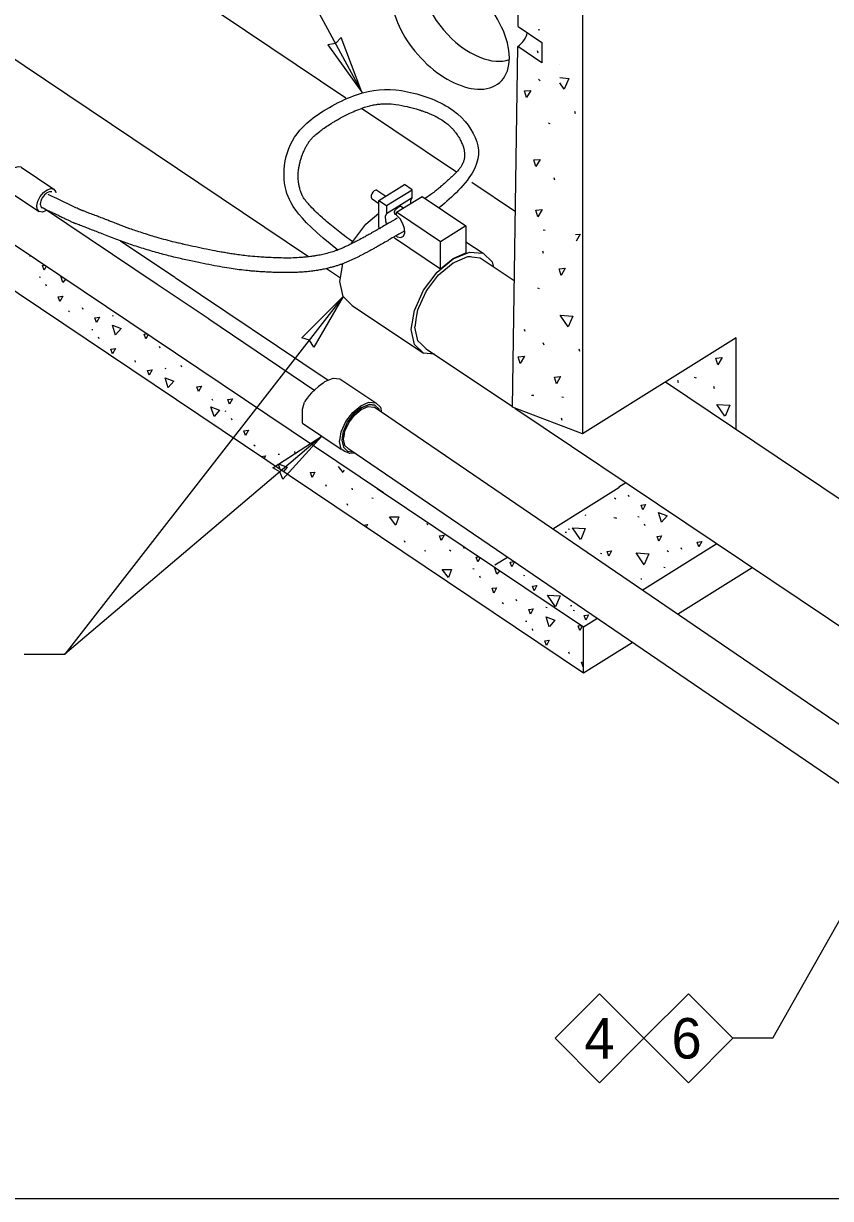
# Model space of a CAD drawing. Extents: x 99862 to 103151, y 100000 to 105076.
# Drawn here: x 100809.4 to 101128.2, y 99999.5 to 100464 of the extents above; entities that cross this region are included whole.
import ezdxf

# ---------------------------------------------------------------- set-up
doc = ezdxf.new("R2010")
doc.units = 0
for name, color, linetype in [('Level 1', 7, 'Continuous'), ('Level 15', 7, 'Continuous'), ('Level 2', 7, 'Continuous'), ('Level 20', 7, 'Continuous'), ('Level 8', 7, 'Continuous')]:
    doc.layers.add(name, color=color, linetype=linetype)

msp = doc.modelspace()

# ---------------------------------------------------------------- linework, layer by layer
at = {"layer": 'Level 1'}
for p, q in [((100936.81, 100434.51), (100849.22, 100493.32)), ((100921.97, 100371.81), (100800.85, 100453.13)), ((101014.18, 100448.5), (101004.66, 100454.89)), ((100980.47, 100405.2), (100942.89, 100430.43)), ((101003.74, 100389.58), (100986.55, 100401.12)), ((100949.04, 100398.08), (100952.56, 100395.72)), ((100817.7, 100390.84), (100862.21, 100360.96)), ((100958.45, 100391.76), (100959.5, 100391.06)), ((100956.59, 100388.37), (100956.8, 100388.22)), ((100984.22, 100384), (100974.15, 100377.7)), ((100847.72, 100378.11), (100869.16, 100363.72)), ((100934.61, 100363.32), (100929.15, 100366.99)), ((100989.88, 100371.42), (101003.31, 100362.4)), ((100869.36, 100363.58), (100929.8, 100323)), ((100862.21, 100360.96), (100882.73, 100347.19)), ((100939.25, 100352.56), (100967.44, 100333.63)), ((100882.57, 100347.29), (100924.48, 100318.92)), ((101091, 100303.53), (101091, 100339.79)), ((100968.51, 100335.43), (101002.58, 100312.56)), ((100971.72, 100333.28), (100967.44, 100333.63)), ((101156.62, 100169.88), (100947.9, 100312.28)), ((101003.57, 100311.9), (101182.9, 100191.5)), ((100919.6, 100306.05), (100934.94, 100295.75)), ((101144.52, 100154.73), (100937.9, 100295.69)), ((101053.87, 100239.98), (101083.29, 100258.37)), ((101067.77, 100230.5), (101097.31, 100248.96)), ((101030.63, 100225.46), (101035.96, 100228.79)), ((101030.63, 100207.29), (101049.86, 100219.31))]:
    msp.add_line(p, q, dxfattribs=at)
msp.add_lwpolyline([(99862, 99999.5), (103151, 99999.5), (103151, 102075.5), (99862, 102075.5)], close=True, dxfattribs=at)
for points in [[(101166.34, 100612.08), (101030.25, 100527.03), (101030.25, 100301.82)], [(101004.78, 100462.81), (101005.95, 100543.35), (101005.95, 100543.35)], [(101091, 100339.79), (101030.25, 100301.82), (101002.58, 100312.27), (101004.66, 100454.89), (101005.33, 100455.36), (101005.92, 100455.89), (101006.06, 100456.02), (101006.75, 100456.79), (101007.1, 100457.3), (101007.35, 100457.65), (101007.85, 100458.56), (101007.99, 100458.9), (101008.23, 100459.48), (101008.46, 100460.34)], [(101004.78, 100462.81), (101014.18, 100456.5), (101014.18, 100448.5), (101014.18, 100448.5)], [(100741.42, 100419.72), (100951.61, 100278.54)], [(100735.82, 100405.31), (101030.63, 100207.29)], [(100808.46, 100407.14), (100807.29, 100407.38), (100805.86, 100406.91), (100804.39, 100405.8), (100803.1, 100404.22), (100802.18, 100402.41), (100801.78, 100400.65), (100801.96, 100399.2), (100802.69, 100398.29), (100815.57, 100389.64), (100814.84, 100390.56), (100814.66, 100392), (100815.06, 100393.76), (100815.97, 100395.57), (100817.26, 100397.15), (100818.74, 100398.26), (100820.17, 100398.74), (100821.33, 100398.5)], [(100808.46, 100407.14), (100821.33, 100398.5), (100822.06, 100397.59), (100822.14, 100397.01)], [(100949.84, 100383.37), (100949.84, 100394.02), (100959.92, 100400.32)], [(100962.46, 100392.91), (100962.42, 100393.99), (100962.96, 100395.19), (100962.96, 100398.28), (100959.92, 100400.32)], [(100820.58, 100397.41), (100820.57, 100397.41), (100820.23, 100397.44), (100819.71, 100397.49), (100819.3, 100397.32), (100818.68, 100397.06), (100818.28, 100396.72), (100817.66, 100396.21), (100817.32, 100395.75), (100816.79, 100395.05), (100816.56, 100394.54), (100816.21, 100393.77), (100816.13, 100393.29), (100816.01, 100392.56), (100816.09, 100392.18), (100816.21, 100391.61), (100816.44, 100391.38), (100816.79, 100391.05), (100816.79, 100391.05)], [(100949.04, 100398.08), (100948.56, 100398.07), (100948.01, 100397.79), (100947.48, 100397.31), (100947.05, 100396.67), (100946.78, 100396), (100946.71, 100395.38), (100946.86, 100394.91), (100947.2, 100394.67), (100949.84, 100392.89)], [(100949.84, 100394.02), (100952.88, 100391.98), (100962.96, 100398.28)], [(100952.88, 100391.98), (100952.88, 100388.89), (100962.96, 100395.19)], [(100959.5, 100379.97), (100960.03, 100381.19), (100959.96, 100382.89), (100959.33, 100384.84), (100958.21, 100386.72), (100956.78, 100388.25), (100956.78, 100389.36), (100966.85, 100395.66), (100984.22, 100384), (100984.22, 100373.35)], [(100818.64, 100390.24), (100818.17, 100389.88), (100816.74, 100389.41), (100815.57, 100389.64)], [(100956.59, 100388.37), (100956.59, 100388.37), (100956.41, 100388.49), (100956.17, 100388.66), (100956.08, 100388.92), (100956, 100389.14), (100956.04, 100389.66), (100956.05, 100389.77), (100956.16, 100390.07), (100956.33, 100390.29), (100956.41, 100390.39), (100956.97, 100390.94), (100957.25, 100391.16), (100957.55, 100391.39), (100957.68, 100391.46), (100957.99, 100391.63), (100958.07, 100391.68)], [(100958.07, 100391.68), (100958.39, 100391.74), (100958.45, 100391.76), (100958.46, 100391.76)], [(100938.73, 100376.76), (100944.65, 100384.63), (100949.84, 100388.98)], [(100952.88, 100388.89), (100952.35, 100387.69), (100952.4, 100385.99), (100952.86, 100384.58)], [(100974.15, 100367.06), (100974.15, 100377.7), (100956.78, 100389.36)], [(100949.84, 100383.37), (100950.42, 100382.99)], [(100955.92, 100379.29), (100974.15, 100367.06), (100979.18, 100371.03), (100984.22, 100373.35)], [(100956.78, 100379.87), (100957.09, 100379.67), (100958.47, 100379.44), (100959.5, 100379.97)], [(100984.22, 100377.73), (100990.95, 100373.21), (100994.56, 100369.76), (100994.92, 100368.03)], [(100967.44, 100333.63), (100963.84, 100337.09), (100962.57, 100343.03), (100963.84, 100350.56), (100967.44, 100358.52), (100972.84, 100365.71), (100979.2, 100371.02), (100985.56, 100373.66), (100990.95, 100373.21)], [(100968.51, 100335.43), (100968.51, 100335.43), (100968.13, 100335.8), (100966.69, 100337.18), (100965.23, 100338.58), (100965.1, 100339.2), (100964.08, 100343.98), (100964.22, 100344.77), (100964.59, 100347.01), (100964.86, 100348.59), (100965.23, 100350.82), (100965.62, 100351.66), (100967.85, 100356.6), (100968.12, 100357.2), (100968.33, 100357.67), (100968.51, 100358.06), (100969.08, 100358.82), (100973.41, 100364.59), (100974.09, 100365.15), (100979.2, 100369.42), (100979.51, 100369.55), (100979.87, 100369.7), (100984.98, 100371.82), (100985.43, 100371.89), (100985.49, 100371.9), (100985.56, 100371.89), (100985.94, 100371.85), (100986, 100371.85), (100986.53, 100371.79), (100987.64, 100371.66), (100989.88, 100371.42), (100989.88, 100371.41)], [(100939.25, 100352.56), (100935.65, 100356.02), (100934.38, 100361.96), (100935.56, 100368.98)], [(100927.74, 100321.83), (100928.49, 100322.45), (100931.69, 100323.78), (100934.41, 100323.56), (100948.62, 100314.02), (100950.44, 100312.27), (100950.86, 100310.26)], [(101063.03, 100322.31), (101204.27, 100227.48), (101207.55, 100224.34), (101208.54, 100219.7)], [(100919.6, 100306.05), (100919.61, 100311.59), (100920.42, 100314.24)], [(100934.5, 100299.88), (100934.95, 100302.6), (100936.77, 100306.61), (100939.49, 100310.23), (100942.69, 100312.91), (100945.9, 100314.24), (100948.62, 100314.02)], [(100935.43, 100300.42), (100935.81, 100302.71), (100937.46, 100306.35), (100939.94, 100309.65), (100942.85, 100312.08), (100945.77, 100313.29), (100946.02, 100313.33), (100948.24, 100313.09)], [(100936.04, 100300.76), (100936.39, 100302.81), (100937.9, 100306.16), (100940.17, 100309.19), (100942.85, 100311.43), (100945.53, 100312.54), (100947.8, 100312.35), (100947.8, 100312.35)], [(100943.01, 100312.15), (100942.85, 100312.08), (100939.94, 100309.65)], [(100946.06, 100313.33), (100946.02, 100313.33), (100945.77, 100313.29), (100943.01, 100312.15)], [(100950.03, 100310.83), (100949.89, 100311.5), (100948.24, 100313.09), (100947.11, 100313.21), (100946.55, 100313.27), (100946.25, 100313.31)], [(100940.21, 100294.11), (100938.31, 100293.99), (100936.31, 100294.81), (100934.94, 100295.75), (100934.31, 100298.74), (100934.5, 100299.88)], [(100935.62, 100301.56), (100935.49, 100300.77), (100935.23, 100299.24), (100935.81, 100296.51), (100936.54, 100295.81), (100937.46, 100294.93), (100939.14, 100294.69), (100939.3, 100294.74)], [(100937.9, 100295.69), (100936.39, 100297.15), (100935.85, 100299.65), (100936.04, 100300.76)], [(100949.14, 100280.19), (101030.63, 100225.46)], [(101047.41, 100282.46), (101044.61, 100280.71), (101044.61, 100280.39), (101018.53, 100264.09)], [(101000.62, 100252.9), (100995.68, 100249.81)], [(101030.63, 100207.29), (101030.63, 100225.46)]]:
    msp.add_lwpolyline(points, dxfattribs=at)
for centre, major_axis, start_param, end_param in [((100987.06, 100470.58), (17.07, -19.15), 3.926991, 5.418306), ((100978.12, 100462.62), (19.51, -21.88), 5.822747, 7.896333), ((100978.12, 100462.62), (19.51, -21.88), 3.926991, 5.822747), ((100987.06, 100470.58), (17.07, -19.15), 5.418306, 6.066844)]:
    msp.add_ellipse(centre, major_axis=major_axis, ratio=0.57735, start_param=start_param, end_param=end_param, dxfattribs=at)
for points, degree in [([(100933.61, 100374.43), (100916.29, 100387.91), (100910.9, 100400.98), (100913.55, 100415.24), (100920.6, 100425.71), (100941.82, 100437.61), (100957.97, 100438.81), (100979.02, 100431.88), (100989.53, 100418.97), (100989.95, 100405.59), (100977.2, 100393.87), (100973.55, 100391.17)], 3), ([(100939.47, 100377.64), (100935.77, 100380.38), (100932.56, 100382.9), (100926.92, 100387.64), (100924.57, 100389.83), (100922, 100392.57), (100921.3, 100393.4), (100920.22, 100394.81), (100919.85, 100395.4), (100919.58, 100395.91), (100919.53, 100396), (100919.48, 100396.12), (100919.47, 100396.16), (100919.45, 100396.2), (100919.45, 100396.2), (100919.43, 100396.24), (100919.41, 100396.29), (100919.27, 100396.64), (100919.14, 100396.97), (100918.84, 100397.84), (100918.66, 100398.41), (100918.21, 100400.11), (100918.03, 100401.23), (100917.86, 100403.44), (100917.88, 100404.54), (100918.04, 100405.94), (100918.09, 100406.36), (100918.16, 100406.78), (100918.21, 100407.06), (100918.25, 100407.22), (100918.4, 100408.01), (100918.54, 100408.62), (100918.99, 100410.39), (100919.35, 100411.51), (100920.17, 100413.59), (100920.63, 100414.57), (100921.4, 100415.95), (100921.67, 100416.39), (100922.02, 100416.93), (100922.09, 100417.05), (100922.2, 100417.21), (100922.26, 100417.29), (100922.45, 100417.55), (100922.59, 100417.73), (100923.38, 100418.68), (100924.26, 100419.57), (100926.57, 100421.5), (100927.99, 100422.55), (100930.51, 100424.19), (100931.41, 100424.75), (100932.86, 100425.61), (100933.36, 100425.89), (100934.39, 100426.48), (100934.9, 100426.76), (100937.41, 100428.11), (100939.32, 100429.01), (100942.89, 100430.47), (100944.56, 100431.03), (100946.88, 100431.62), (100947.62, 100431.78), (100948.67, 100431.96), (100949.02, 100432.01), (100949.52, 100432.07), (100949.77, 100432.1), (100950.02, 100432.12), (100950.18, 100432.13), (100950.26, 100432.14), (100953.05, 100432.35), (100956.18, 100432.13), (100961.52, 100431.05), (100963.41, 100430.57), (100965.64, 100429.88), (100966.01, 100429.76), (100966.39, 100429.64), (100966.64, 100429.55), (100966.76, 100429.51), (100967.37, 100429.31), (100967.84, 100429.15), (100969.21, 100428.63), (100970.08, 100428.27), (100972.54, 100427.15), (100973.98, 100426.34), (100976.51, 100424.62), (100977.59, 100423.71), (100978.75, 100422.52), (100978.97, 100422.28), (100979.29, 100421.91), (100979.39, 100421.79), (100979.6, 100421.54), (100979.71, 100421.4), (100980.25, 100420.71), (100980.65, 100420.17), (100981.7, 100418.58), (100982.24, 100417.56), (100983.06, 100415.6), (100983.33, 100414.66), (100983.57, 100413.28), (100983.62, 100412.82), (100983.65, 100412.25), (100983.66, 100412.13), (100983.66, 100411.94), (100983.66, 100411.84), (100983.66, 100411.56), (100983.65, 100411.37), (100983.56, 100410.44), (100983.39, 100409.73), (100982.73, 100408.18), (100982.25, 100407.34), (100981.2, 100406), (100980.8, 100405.54), (100980.12, 100404.83), (100979.87, 100404.6), (100979.55, 100404.29), (100979.49, 100404.24), (100979.33, 100404.09), (100979.08, 100403.87), (100977.57, 100402.48), (100976.26, 100401.31), (100974.16, 100399.46), (100973.22, 100398.66), (100971.56, 100397.28), (100970.84, 100396.72), (100968.15, 100394.79)], 3), ([(100832.02, 100390.28), (100831.97, 100390.3), (100831.81, 100390.37), (100831.38, 100390.56), (100831.1, 100390.69), (100830.09, 100391.15), (100829.21, 100391.56), (100825.94, 100393.12), (100822.95, 100394.57), (100819.16, 100396.42)], 3), ([(100960, 100382.04), (100960, 100382.04), (100944.12, 100372.82), (100932.97, 100367.7), (100919.09, 100365.27), (100900.53, 100365.82), (100885.19, 100367.98), (100858.32, 100373.96), (100831.38, 100384.36), (100828.72, 100385.3), (100816.62, 100391.22)], 2), ([(100957.09, 100387.05), (100957.04, 100387.02), (100954.38, 100385.48), (100948.97, 100382.33), (100948.81, 100382.24), (100948.49, 100382.06), (100948.01, 100381.78), (100946.92, 100381.16), (100946.01, 100380.64), (100944.23, 100379.65), (100943.09, 100379.03), (100939.84, 100377.31), (100937.89, 100376.34), (100936.1, 100375.51), (100936.05, 100375.49), (100935.95, 100375.45), (100935.8, 100375.38), (100935.44, 100375.22), (100934.72, 100374.91), (100934.09, 100374.66), (100932.8, 100374.18), (100931.91, 100373.87), (100929.14, 100373.04), (100927.17, 100372.57), (100924.81, 100372.16), (100924.56, 100372.11), (100924.03, 100372.03), (100923.23, 100371.91), (100922.39, 100371.8), (100920.68, 100371.61), (100919.48, 100371.51), (100915.73, 100371.28), (100913, 100371.25), (100909.7, 100371.34), (100909.32, 100371.36), (100908.58, 100371.38), (100907.47, 100371.42), (100904.94, 100371.54), (100902.84, 100371.68), (100898.76, 100372.01), (100896.19, 100372.28), (100893.15, 100372.71), (100892.52, 100372.8), (100891.18, 100373.01), (100890.48, 100373.13), (100888.29, 100373.5), (100886.7, 100373.79), (100881.55, 100374.78), (100877.62, 100375.6), (100872.66, 100376.7), (100872.12, 100376.82), (100871.04, 100377.08), (100869.42, 100377.46), (100865.63, 100378.41), (100862.38, 100379.33), (100855.87, 100381.31), (100851.52, 100382.8), (100846.89, 100384.58), (100846.61, 100384.69), (100846.06, 100384.91), (100845.25, 100385.22), (100843.43, 100385.92), (100842.02, 100386.46), (100839.39, 100387.48), (100837.88, 100388.06), (100835.37, 100389.02), (100834.37, 100389.4), (100833.23, 100389.83), (100832.92, 100389.95), (100832.39, 100390.14), (100832.2, 100390.22), (100832.02, 100390.28)], 3), ([(100927.74, 100321.83), (100922.54, 100318.17), (100920.69, 100314.83), (100920.42, 100314.24)], 3)]:
    msp.add_open_spline(points, degree=degree, dxfattribs=at)
at = {"layer": 'Level 15'}
for p, q in [((100888.86, 100537.41), (100943.04, 100436.88)), ((100935.65, 100356.02), (100825.67, 100214.63)), ((100927.27, 100300.9), (100825.67, 100214.63)), ((100809.67, 100214.63), (100825.67, 100214.63)), ((101152.76, 100146.86), (101105.5, 100062.98)), ((101105.65, 100062.82), (101089.65, 100062.82))]:
    msp.add_line(p, q, dxfattribs=at)
for points in [[(100943.04, 100436.88), (100934.86, 100458.4), (100932.73, 100456.06), (100929.6, 100455.58)], [(100935.65, 100356.02), (100924.09, 100336.1), (100922.37, 100338.76), (100919.36, 100339.74)], [(100927.27, 100300.9), (100911.8, 100283.85), (100910.68, 100286.81), (100907.94, 100288.4)]]:
    msp.add_lwpolyline(points, close=True, dxfattribs=at)
at = {"layer": 'Level 2'}
msp.add_lwpolyline([(101021.3, 100447.67), (101021.3, 100447.67)], dxfattribs=at)
at = {"layer": 'Level 20'}
for points in [[(101036.99, 100080.38), (101054.55, 100062.82), (101036.99, 100045.27), (101019.44, 100062.82)], [(101072.1, 100080.38), (101089.65, 100062.82), (101072.1, 100045.27), (101054.55, 100062.82)]]:
    msp.add_lwpolyline(points, close=True, dxfattribs=at)
at = {"layer": 'Level 8'}
for p, q in [((101012.69, 100461.6), (101013.37, 100461.42)), ((101012.81, 100452.26), (101012.52, 100453.18)), ((101012.9, 100441.93), (101013.56, 100441.34)), ((101027.49, 100428.24), (101027.2, 100429.16)), ((101016.69, 100424.67), (101017.37, 100424.49)), ((101019.31, 100402.05), (101019.01, 100402.97)), ((101014.77, 100382.42), (101015.46, 100382.24)), ((100812.13, 100371.69), (100811.88, 100372.35)), ((101014.89, 100373.08), (101014.6, 100374)), ((100818.32, 100368.07), (100817.51, 100366.52)), ((100815.55, 100363.86), (100816.05, 100363.76)), ((100824.93, 100361.6), (100824.15, 100364.15)), ((100826.03, 100362.89), (100824.98, 100361.65)), ((100818.48, 100360.17), (100818.23, 100360.83)), ((101012.45, 100359.45), (101013.13, 100359.27)), ((100827.12, 100350.44), (100827.63, 100350.03)), ((100832.92, 100350.9), (100832.67, 100351.56)), ((100844.39, 100348.56), (100844.89, 100348.46)), ((100836.34, 100343.07), (100836.84, 100342.97)), ((100839.27, 100339.38), (100839.02, 100340.04)), ((100858.63, 100340.99), (100857.76, 100339.34)), ((100863.41, 100335.69), (100863.16, 100336.34)), ((101015.07, 100336.83), (101014.77, 100337.75)), ((101029.26, 100334.36), (101028.96, 100335.27)), ((100853.71, 100330.11), (100853.46, 100330.76)), ((100865.18, 100327.77), (100865.68, 100327.67)), ((100871.94, 100328.16), (100871.69, 100328.81)), ((101068.21, 100322), (101067.91, 100322.92)), ((101074.44, 100324.14), (101075.12, 100323.96)), ((101082.4, 100319.53), (101082.1, 100320.45)), ((101010.09, 100317.1), (101010.74, 100316.94)), ((101010.53, 100317.2), (101010.99, 100317.08)), ((101022.12, 100316.39), (101022.81, 100316.21)), ((100884.2, 100314.9), (100883.95, 100315.55)), ((100888.89, 100310.85), (100889.39, 100310.75)), ((100891.82, 100307.16), (100891.57, 100307.81)), ((101022.24, 100307.05), (101021.95, 100307.97)), ((100900.46, 100297.42), (100900.97, 100297.02)), ((100910.03, 100293.8), (100910.53, 100293.7)), ((100916.79, 100294.19), (100916.54, 100294.84)), ((100935.68, 100286.52), (100933.92, 100288.84)), ((100936.02, 100287.43), (100935.71, 100286.58)), ((100929.05, 100280.92), (100928.8, 100281.58)), ((100939.45, 100279.67), (100939.19, 100280.32)), ((100937.58, 100273.4), (100937.33, 100274.05)), ((100947.08, 100276.46), (100947.58, 100276.36)), ((101042.88, 100276.43), (101043.38, 100276.02)), ((101048.68, 100276.89), (101048.43, 100277.55)), ((101031.12, 100269.7), (101031.63, 100269.6)), ((100969.12, 100265.67), (100968.87, 100266.32)), ((101052.1, 100269.06), (101052.6, 100268.96)), ((101055.03, 100265.37), (101054.78, 100266.03)), ((101023.42, 100262.95), (101023.93, 100262.85)), ((101024.64, 100264.25), (101025.14, 100264.15)), ((100960.24, 100258.88), (100959.99, 100259.53)), ((100967.87, 100255.67), (100968.37, 100255.57)), ((100977.76, 100255.93), (100978.27, 100255.53)), ((100983.56, 100256.4), (100983.31, 100257.05)), ((101063.67, 100255.64), (101064.18, 100255.23)), ((101069.47, 100256.1), (101069.22, 100256.75)), ((100989.8, 100252.88), (100988.94, 100251.22)), ((101037.35, 100254.64), (101037.85, 100254.54)), ((100986.98, 100248.57), (100987.49, 100248.47)), ((100996.36, 100246.3), (100995.52, 100249.04)), ((100997.54, 100247.69), (100996.41, 100246.35)), ((101062.44, 100249.1), (101062.94, 100249)), ((100989.91, 100244.87), (100989.66, 100245.53)), ((101006.9, 100245.9), (101007.41, 100245.8)), ((101006.9, 100245.9), (101007.41, 100245.8)), ((101053.27, 100244.52), (101053.77, 100244.42)), ((100998.55, 100235.14), (100999.06, 100234.74)), ((101004.35, 100235.6), (101004.1, 100236.26)), ((101015.82, 100233.26), (101016.32, 100233.16)), ((101025.5, 100233.96), (101026, 100233.86)), ((101007.77, 100227.78), (101008.28, 100227.68)), ((101026.63, 100232.05), (101027.13, 100231.95)), ((101010.7, 100224.08), (101010.45, 100224.74)), ((101030.12, 100225.8), (101029.2, 100224.04)), ((101025.14, 100214.81), (101024.89, 100215.47)), ((101030.63, 100209.85), (101030.52, 100209.64))]:
    msp.add_line(p, q, dxfattribs=at)
for points in [[(101021.3, 100442.59), (101024.91, 100442.28), (101023.02, 100438.07)], [(101008.17, 100434.71), (101007.4, 100437.31), (101009.84, 100437.53), (101008.17, 100434.71)], [(101022.98, 100437.99), (101021.3, 100440.56)], [(101011.83, 100407.47), (101011.06, 100410.07), (101013.49, 100410.29), (101011.83, 100407.47)], [(101012.6, 100387.6), (101011.84, 100390.2), (101014.27, 100390.42), (101012.6, 100387.6)], [(101027.51, 100380.54), (101029.39, 100380.71), (101027.73, 100377.89)], [(100817.51, 100366.52), (100816.85, 100368.38), (100817.68, 100368.5)], [(101021.77, 100364.42), (101021.01, 100367.02), (101023.44, 100367.24), (101021.77, 100364.42)], [(100823.81, 100354.15), (100823.15, 100356), (100824.91, 100356.25), (100823.81, 100354.15)], [(101024.58, 100344.03), (101021.42, 100348.7), (101026.43, 100348.36), (101024.62, 100344.12)], [(100838.3, 100345.73), (100837.64, 100347.59), (100839.4, 100347.84), (100838.3, 100345.73)], [(100845.72, 100340.81), (100844.52, 100344.73), (100847.93, 100343.42), (100845.77, 100340.86)], [(100857.76, 100339.34), (100857.11, 100341.2), (100858.11, 100341.34)], [(101007.59, 100342.25), (101007.37, 100342.98)], [(100844.6, 100333.35), (100843.94, 100335.21), (100845.7, 100335.46), (100844.6, 100333.35)], [(101005.65, 100329.61), (101004.88, 100332.21), (101007.32, 100332.42), (101005.65, 100329.61)], [(101083.76, 100329.11), (101083, 100331.71), (101085.43, 100331.93), (101083.76, 100329.11)], [(100859.09, 100324.94), (100858.43, 100326.8), (100860.19, 100327.05), (100859.09, 100324.94)], [(100866.51, 100320.02), (100865.31, 100323.94), (100868.73, 100322.63), (100866.56, 100320.07)], [(100878.56, 100318.55), (100877.9, 100320.41), (100879.66, 100320.66), (100878.56, 100318.55)], [(101019.95, 100321.57), (101019.19, 100324.17), (101021.62, 100324.39), (101019.95, 100321.57)], [(100884.68, 100308.59), (100883.47, 100312.51), (100886.89, 100311.2), (100884.73, 100308.64)], [(100890.85, 100313.5), (100890.19, 100315.36), (100891.95, 100315.61), (100890.85, 100313.5)], [(101086.56, 100308.72), (101083.4, 100313.39), (101088.42, 100313.05), (101086.61, 100308.81)], [(100897.15, 100301.13), (100896.49, 100302.99), (100898.25, 100303.24), (100897.15, 100301.13)], [(100903.28, 100292.82), (100903.28, 100292.82), (100905.04, 100293.08), (100904.49, 100292.01)], [(100910.84, 100287.74), (100910.16, 100289.97), (100913.58, 100288.66), (100912.09, 100286.9)], [(100923.41, 100284.58), (100922.75, 100286.44), (100924.51, 100286.69), (100923.41, 100284.58)], [(101054.06, 100271.72), (101053.4, 100273.58), (101055.16, 100273.83), (101054.06, 100271.72)], [(101061.48, 100266.8), (101060.28, 100270.72), (101063.69, 100269.41), (101061.53, 100266.85)], [(100943.71, 100265.67), (100945.3, 100265.9), (100944.8, 100264.94)], [(100956.47, 100265.73), (100954, 100269), (100957.65, 100268.94), (100956.5, 100265.79)], [(101042.7, 100268.66), (101043.56, 100268.64), (101043.4, 100268.19)], [(100974.45, 100259.64), (100973.79, 100261.5), (100975.55, 100261.75), (100974.45, 100259.64)], [(101029.52, 100259.98), (101026.36, 100264.65), (101031.38, 100264.3), (101029.57, 100260.07)], [(101060.36, 100259.34), (101059.7, 100261.2), (101061.46, 100261.45), (101060.36, 100259.34)], [(101040.63, 100253.44), (101039.97, 100255.3), (101041.73, 100255.55), (101040.63, 100253.44)], [(101076.27, 100257.17), (101075.61, 100259.02), (101077.37, 100259.28), (101076.27, 100257.17)], [(100988.94, 100251.22), (100988.28, 100253.08), (100989.29, 100253.22)], [(101002.31, 100249.2), (101001.65, 100251.06), (101003.41, 100251.31), (101002.31, 100249.2)], [(101054.63, 100250.05), (101051.47, 100254.72), (101056.48, 100254.37), (101054.67, 100250.13)], [(101074.22, 100252.7), (101074.19, 100252.79), (101074.41, 100252.82)], [(100977.26, 100244.94), (100974.79, 100248.2), (100978.44, 100248.15), (100977.29, 100245)], [(101011.13, 100239.68), (101010.48, 100241.54), (101012.24, 100241.79), (101011.13, 100239.68)], [(100995.24, 100238.85), (100994.58, 100240.71), (100996.34, 100240.96), (100995.24, 100238.85)], [(101019.54, 100233.36), (101016.38, 100238.03), (101021.39, 100237.68), (101019.58, 100233.45)], [(101009.73, 100230.43), (101009.07, 100232.29), (101010.83, 100232.54), (101009.73, 100230.43)], [(101017.15, 100225.51), (101015.95, 100229.43), (101019.37, 100228.13), (101017.21, 100225.56)], [(101031.54, 100228.08), (101030.89, 100229.94), (101032.65, 100230.19), (101031.54, 100228.08)], [(101029.2, 100224.04), (101028.54, 100225.9), (101029.72, 100226.07)], [(101016.03, 100218.06), (101015.37, 100219.92), (101017.13, 100220.17), (101016.03, 100218.06)], [(101030.52, 100209.64), (101029.86, 100211.5), (101030.63, 100211.61)]]:
    msp.add_lwpolyline(points, dxfattribs=at)

# ---------------------------------------------------------------- texts
at = {"layer": 'Level 20'}
for s, p in [('4', (101030.99, 100054.83)), ('6', (101065.44, 100054.83))]:
    msp.add_text(s, height=16, dxfattribs=at).set_placement(p)

doc.saveas('drawing.dxf')
